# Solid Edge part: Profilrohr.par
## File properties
Username: bmolnar
Dokumentum tartalom típus: 0
Author: bmolnar
Last saved by: bmolnar
Revision: 87
Sűrűség: 0,000 kg/m^3
Pontosság: 0,990
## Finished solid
Body 1: solid body, 115 faces, 338 edges, 224 vertices.
  Faces by surface: cylinder 59, plane 56
  Edges by curve: line 220, circle 118
Bounding box of the edges (mm): 113.500 x 113.500 x 108.000, from (-56.75, -56.75, -91.5) to (56.75, 56.75, 16.5).
Cylindrical faces by radius (mm): R0.15 x24, R0.25 x24, R1 x4, R12.25 x4, R35 x2, R50 x1
Planar faces by outward normal: +x 13, +y 14, +z 1, -x 13, -y 14, -z 1
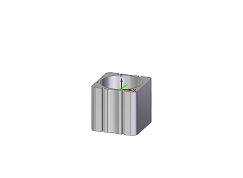
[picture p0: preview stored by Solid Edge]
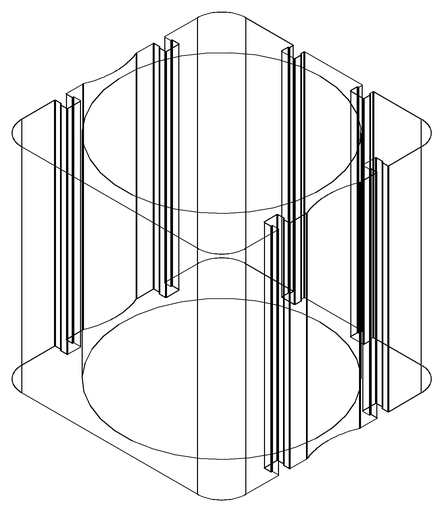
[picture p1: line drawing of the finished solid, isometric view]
